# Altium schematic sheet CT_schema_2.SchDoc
size 206 x 169 mm
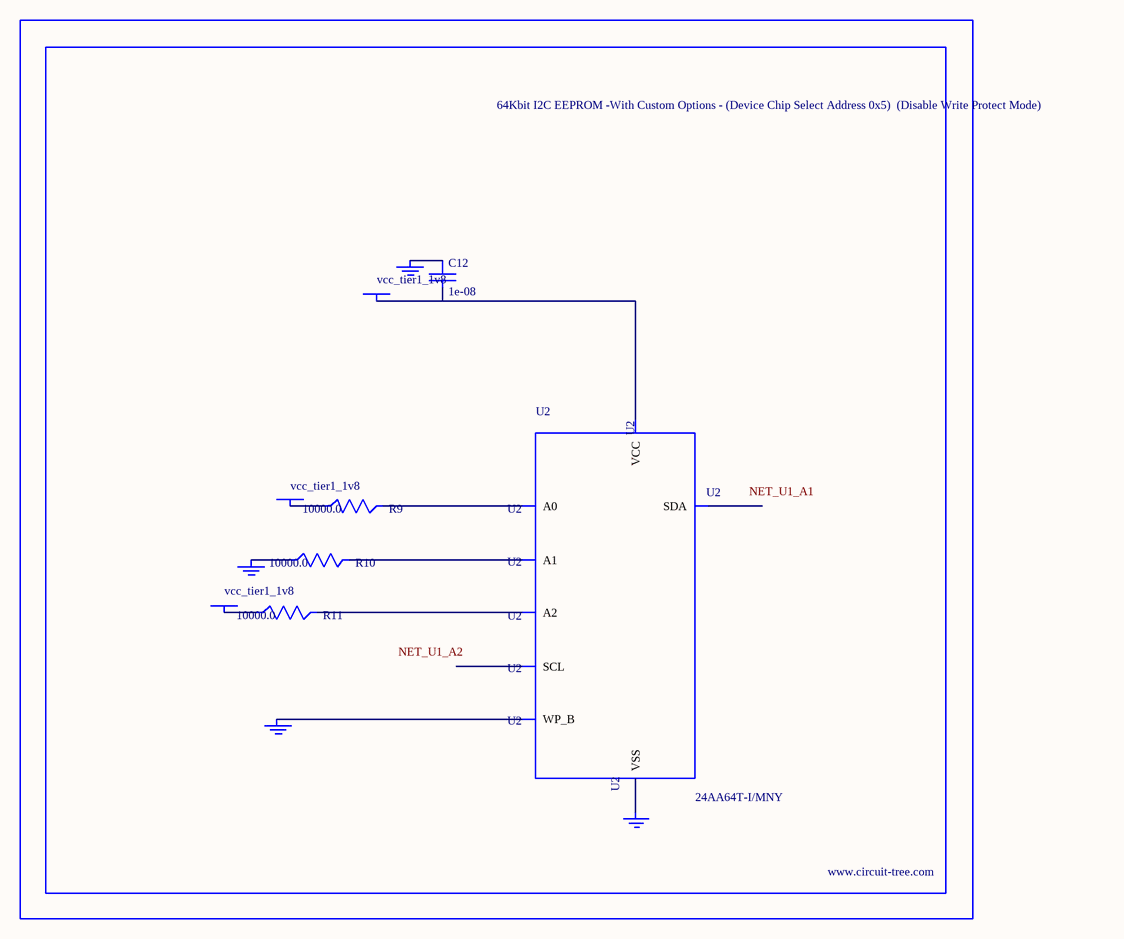
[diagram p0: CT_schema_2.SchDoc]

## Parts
BORDER1  (no value)
C12  1e-08  [C0402]
GND_INSTANCE_1_0  (no value)
GND_INSTANCE_1_1  (no value)
GND_INSTANCE_1_2  (no value)
GND_INSTANCE_1_3  (no value)
POWER_INSTANCE_1_0  vcc_tier1_1v8
POWER_INSTANCE_1_1  vcc_tier1_1v8
POWER_INSTANCE_1_2  vcc_tier1_1v8
R9  10000.0  [R0603]
R10  10000.0  [R0603]
R11  10000.0  [R0603]
U2  24AA64T-I/MNY  [TDFN-8/6MM]

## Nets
NetC12_1: C12.1 GND_INSTANCE_1_2.0(GND)
NetC12_2: C12.2 POWER_INSTANCE_1_2.0(PWR) U2.8(VCC)
NetGND_INSTANCE_1_0_0: GND_INSTANCE_1_0.0(GND) R10.1
NetGND_INSTANCE_1_1_0: GND_INSTANCE_1_1.0(GND) U2.7(WP_B)
NetGND_INSTANCE_1_3_0: GND_INSTANCE_1_3.0(GND) U2.4(VSS)
NetPOWER_INSTANCE_1_0_0: POWER_INSTANCE_1_0.0(PWR) R9.1
NetPOWER_INSTANCE_1_1_0: POWER_INSTANCE_1_1.0(PWR) R11.1
NetR9_2: R9.2 U2.1(A0)
NetR10_2: R10.2 U2.2(A1)
NetR11_2: R11.2 U2.3(A2)

Not connected (* = marked no-connect by the designer): U2 5(SDA) 6(SCL)

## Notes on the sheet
- Labels drawn without touching a wire or pin: NET_U1_A1, NET_U1_A2

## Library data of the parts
BORDER1 = BORDER_PAGE1
C12 = C0402C103K3RAC
GND_INSTANCE_1_0-GND_INSTANCE_1_3 = GND
POWER_INSTANCE_1_0-POWER_INSTANCE_1_2 = PWR
R9-R11 = RC0603JR-0710KL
